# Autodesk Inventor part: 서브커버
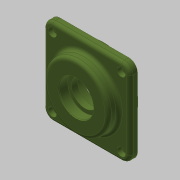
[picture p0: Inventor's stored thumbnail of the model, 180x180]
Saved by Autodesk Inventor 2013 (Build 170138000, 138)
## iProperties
Created: 2018-09
Part Number: 서브커버
Material: 일반
Document SubType Name: Modeling
Designer: mduedu
Density: 1 g/cm^3
Author: mduedu
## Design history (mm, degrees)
sketch "스케치1"
  geometry: L1 (-40, -40)-(40, -40); L2 (40, -40)-(40, 40); L3 (40, 40)-(-40, 40); L4 (-40, 40)-(-40, -40); L5 (-40, -40)-(40, 40); L6 (40, -40)-(-40, 40); 1 further point
  constraints: 12 end point, 2 midpoint, 2 parallel, 1 horizontal, 1 perpendicular
  dimensions: "d0" = 80 distance of L3.end L2.end; "d1" = 80 distance of L2.end L1.end
extrude "돌출1" new body sketch "스케치1" distance "d2" = 7; taper "d3" = 0 deg
sketch "스케치2"
  geometry: C1 r 30 at (0, 0); 1 further point
  constraints: 1 centre point, 1 coincident
  dimensions: "d4" = 60 diameter of C1
extrude "돌출2" join sketch "스케치2" distance "d5" = 10; taper "d6" = 0 deg
sketch "스케치3"
  geometry: C1 r 32.5 at (0, 0); 1 further point
  constraints: 1 centre point, 1 coincident
  dimensions: "d7" = 65 diameter of C1
extrude "돌출3" join sketch "스케치3" distance "d8" = 9; taper "d9" = 0 deg
sketch "스케치4"
  geometry: L1 (-32.5, -9)-(32.5, -9) reference; L2 (30, 17)-(-30, 17) reference; L3 (0, 17)-(0, -9); L4 (0, -9)-(20, -9); L5 (20, -9)-(20, 3); L6 (20, 3)-(0, 3); L7 (0, 3)-(0, -9); L8 (0, 3)-(12.5, 3); L9 (12.5, 3)-(12.5, 8.7); L10 (12.5, 8.7)-(0, 8.7); L11 (0, 8.7)-(0, 3); L12 (0, 8.7)-(16, 8.7); L13 (16, 8.7)-(16, 17); L14 (16, 17)-(0, 17); L15 (0, 17)-(0, 8.7); 1 further point
  constraints: 26 end point, 6 parallel, 3 horizontal, 3 perpendicular, 2 midpoint, 1 point on line
  dimensions: "d10" = 12 distance of L4.end L5.end; "d12" = 8.3 distance of L12.end L13.end; "d13" = 32 diameter of L13 L3; "d14" = 25 diameter of L9 L3; "d15" = 40 diameter of L5 L3
revolve "회전1" sketch "스케치4" stored, may be unused: angle "d16" = 90 deg
fillet "모깎기1" dims "d17" = 8
fillet "모깎기2" dims "d18" = 3
fillet "모깎기3" dims "d19" = 3
chamfer "모따기1" distance "d20" = 0.8; stored, may be unused: second distance "d21" = 2, angle "d22" = 30 deg
chamfer "모따기2" distance "d23" = 1; stored, may be unused: second distance "d24" = 2, angle "d25" = 30 deg
fillet "모깎기4" dims "d26" = 0.3
sketch "스케치5"
  geometry: A1 r 8 centre (-32, 32) between (-32, 40) and (-40, 32) reference; A2 r 8 centre (-32, -32) between (-40, -32) and (-32, -40) reference; A3 r 8 centre (32, -32) between (32, -40) and (40, -32) reference; A4 r 8 centre (32, 32) between (40, 32) and (32, 40) reference; 5 further points
  constraints: 4 coincident
hole "구멍1" sketch "스케치5" at (-32, 32), (32, 32), (32, -32), (-32, -32) diameter "d27" = 4.5; stored, may be unused: countersink angle "d31" = 90 deg, drill point angle "d33" = 118 deg; dims "d28" = 6, "d29" = 8, "d30" = 4.4, "d32" = 8
node "솔리드1"
